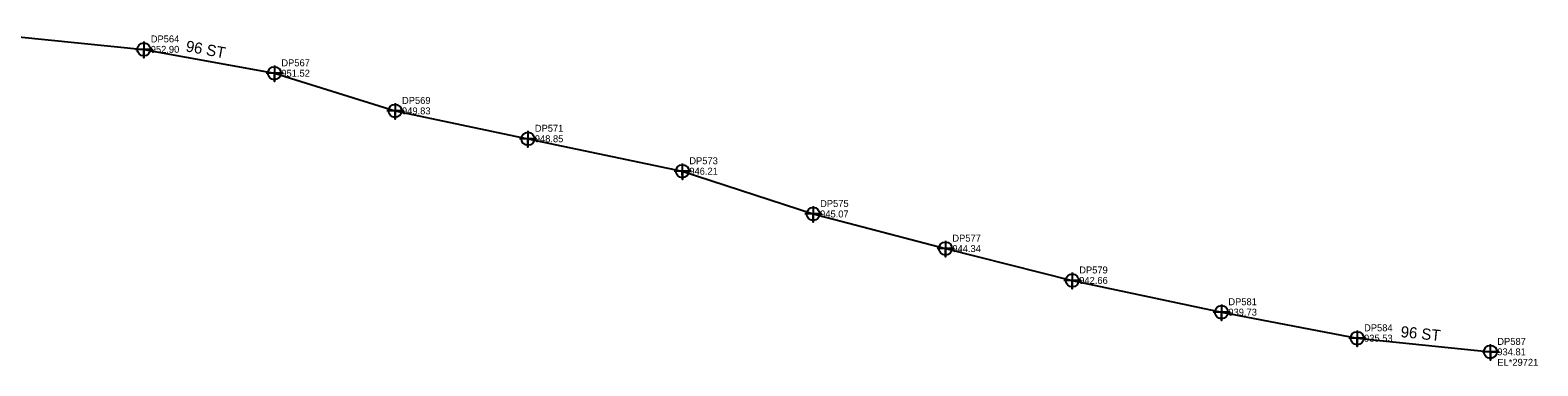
# Model space of a CAD drawing. Extents: x 1182504 to 1186036, y 573002 to 575111.
# Drawn here: x 1185496 to 1186036, y 573591 to 573712 of the extents above; entities that cross this region are included whole.
import ezdxf

# ---------------------------------------------------------------- set-up
doc = ezdxf.new("R2010")
doc.units = 0
for name, color, linetype in [('Exist Utilities Telephone UG Conduit SUE LOS B', 7, 'Continuous'), ('Exist Utilities Telephone UG Conduit SUE LOS B Cogo Comment', 7, 'Continuous'), ('Exist Utilities Telephone UG Conduit SUE LOS B Cogo Elevation', 7, 'Continuous'), ('Exist Utilities Telephone UG Conduit SUE LOS B Cogo Number', 7, 'Continuous'), ('Exist Utilities Telephone UG Conduit SUE LOS B Cogo Point CELL', 7, 'Continuous'), ('Exist Utilities Telephone UG Conduit SUE LOS B Text', 7, 'Continuous')]:
    doc.layers.add(name, color=color, linetype=linetype)

msp = doc.modelspace()

# ---------------------------------------------------------------- linework, layer by layer
at = {"layer": 'Exist Utilities Telephone UG Conduit SUE LOS B'}
msp.add_lwpolyline([(1185467.66, 573711.88), (1185536.39, 573704.97), (1185583.2, 573696.39), (1185626.44, 573682.88), (1185674.04, 573672.89), (1185729.41, 573661.23), (1185776.29, 573645.88), (1185823.7, 573633.45), (1185869.16, 573622.03), (1185922.62, 573610.63), (1185971.26, 573601.28), (1186019.01, 573596.38)], dxfattribs=at)
at = {"layer": 'Exist Utilities Telephone UG Conduit SUE LOS B Cogo Point CELL'}
for points in [[(1185536.38, 573707.78), (1185536.41, 573701.97), (1185536.39, 573704.97), (1185539.41, 573704.97), (1185533.41, 573704.97)], [(1185583.19, 573699.2), (1185583.22, 573693.39), (1185583.2, 573696.39), (1185586.22, 573696.39), (1185580.22, 573696.39)], [(1185626.43, 573685.7), (1185626.46, 573679.88), (1185626.44, 573682.88), (1185629.46, 573682.88), (1185623.46, 573682.88)], [(1185674.02, 573675.7), (1185674.06, 573669.89), (1185674.04, 573672.89), (1185677.06, 573672.89), (1185671.06, 573672.89)], [(1185729.39, 573664.04), (1185729.43, 573658.23), (1185729.41, 573661.23), (1185732.43, 573661.23), (1185726.43, 573661.23)], [(1185776.28, 573648.69), (1185776.31, 573642.88), (1185776.29, 573645.88), (1185779.31, 573645.88), (1185773.31, 573645.88)], [(1185823.69, 573636.26), (1185823.72, 573630.45), (1185823.7, 573633.45), (1185826.72, 573633.45), (1185820.72, 573633.45)], [(1185869.15, 573624.84), (1185869.18, 573619.03), (1185869.16, 573622.03), (1185872.18, 573622.03), (1185866.18, 573622.03)], [(1185922.6, 573613.44), (1185922.64, 573607.63), (1185922.62, 573610.63), (1185925.64, 573610.63), (1185919.64, 573610.63)], [(1185971.25, 573604.09), (1185971.28, 573598.28), (1185971.26, 573601.28), (1185974.28, 573601.28), (1185968.28, 573601.28)], [(1186019, 573599.2), (1186019.03, 573593.38), (1186019.01, 573596.38), (1186022.03, 573596.38), (1186016.03, 573596.38)]]:
    msp.add_lwpolyline(points, dxfattribs=at)
for centre in [(1185536.41, 573704.97), (1185583.22, 573696.39), (1185626.46, 573682.88), (1185674.06, 573672.89), (1185729.43, 573661.23), (1185776.31, 573645.88), (1185823.72, 573633.45), (1185869.18, 573622.03), (1185922.64, 573610.63), (1185971.28, 573601.28), (1186019.03, 573596.38)]:
    msp.add_circle(centre, 2.34, dxfattribs=at)

# ---------------------------------------------------------------- texts
at = {"layer": 'Exist Utilities Telephone UG Conduit SUE LOS B Cogo Comment'}
msp.add_text('EL*29721', height=2.5, dxfattribs=at).set_placement((1186021.51, 573591.38))
at = {"layer": 'Exist Utilities Telephone UG Conduit SUE LOS B Cogo Elevation'}
for s, p in [('952.90', (1185538.89, 573703.72)), ('951.52', (1185585.7, 573695.14)), ('949.83', (1185628.94, 573681.63)), ('948.85', (1185676.54, 573671.64)), ('946.21', (1185731.91, 573659.98)), ('945.07', (1185778.79, 573644.63)), ('944.34', (1185826.2, 573632.2)), ('942.66', (1185871.66, 573620.78)), ('939.73', (1185925.12, 573609.38)), ('935.53', (1185973.76, 573600.03)), ('934.81', (1186021.51, 573595.13))]:
    msp.add_text(s, height=2.5, dxfattribs=at).set_placement(p)
at = {"layer": 'Exist Utilities Telephone UG Conduit SUE LOS B Cogo Number'}
for s, p in [('DP564', (1185538.89, 573707.47)), ('DP567', (1185585.7, 573698.89)), ('DP569', (1185628.94, 573685.38)), ('DP571', (1185676.54, 573675.39)), ('DP573', (1185731.91, 573663.73)), ('DP575', (1185778.79, 573648.38)), ('DP577', (1185826.2, 573635.95)), ('DP579', (1185871.66, 573624.53)), ('DP581', (1185925.12, 573613.13)), ('DP584', (1185973.76, 573603.78)), ('DP587', (1186021.51, 573598.88))]:
    msp.add_text(s, height=2.5, dxfattribs=at).set_placement(p)
at = {"layer": 'Exist Utilities Telephone UG Conduit SUE LOS B Text'}
for rotation, p in [(349.6124, (1185551.21, 573704.28)), (354.1504, (1185986.72, 573601.7))]:
    msp.add_text('96 ST', height=4, rotation=rotation, dxfattribs=at).set_placement(p)

doc.saveas('drawing.dxf')
